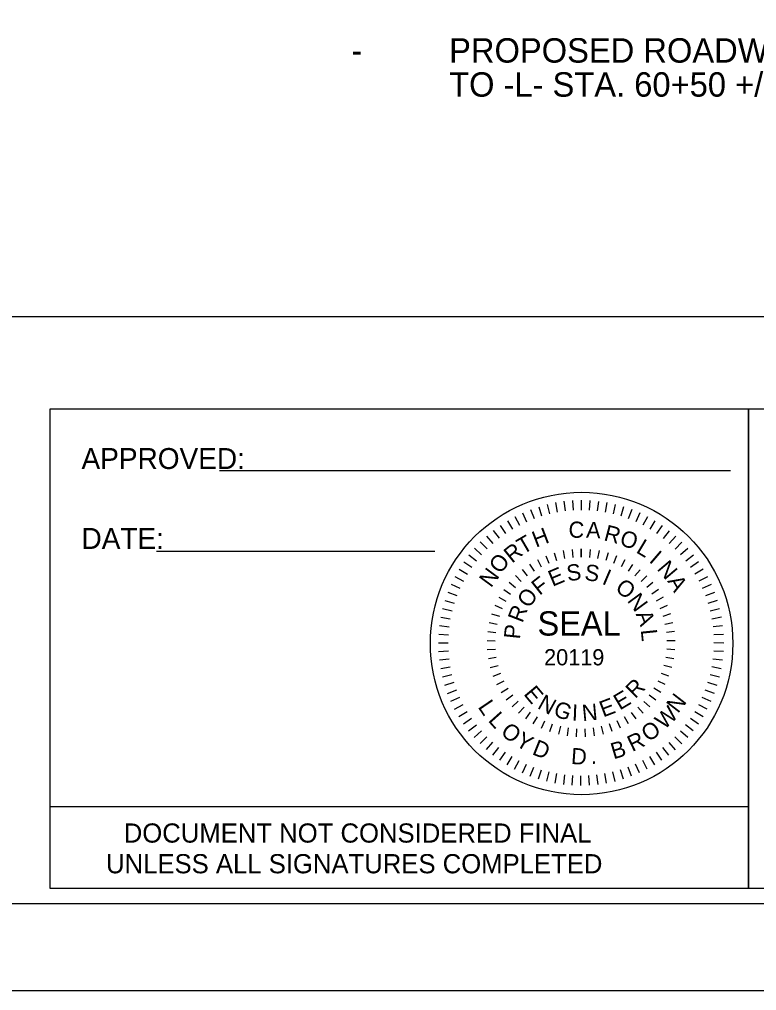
# Model space of a CAD drawing. Extents: x 764226 to 769781, y 650021 to 652521.
# Drawn here: x 767548.3 to 767759.5, y 651421.3 to 651699.7 of the extents above; entities that cross this region are included whole.
import ezdxf

# ---------------------------------------------------------------- set-up
doc = ezdxf.new("R2010")
doc.units = 0
for name, color, linetype in [('Default', 7, 'Continuous'), ('DEV BORDER CELL', 7, 'Continuous'), ('Scratch_Level_0', 7, 'Continuous'), ('Sheet Plot Border Outside CELL', 7, 'Continuous'), ('Sheet Sticker Exception Certification CELL', 7, 'Continuous')]:
    doc.layers.add(name, color=color, linetype=linetype)

msp = doc.modelspace()

# ---------------------------------------------------------------- linework, layer by layer
at = {"layer": 'Default'}
for p, q in [((767697.13, 651559.99), (767697.95, 651557.33)), ((767699.51, 651560.65), (767700.17, 651557.94)), ((767701.92, 651561.17), (767702.42, 651558.43)), ((767704.36, 651561.53), (767704.7, 651558.77)), ((767706.82, 651561.75), (767706.99, 651558.97)), ((767709.29, 651561.83), (767709.29, 651559.04)), ((767711.76, 651561.75), (767711.59, 651558.97)), ((767714.22, 651561.52), (767713.88, 651558.76)), ((767716.66, 651561.15), (767716.16, 651558.41)), ((767719.07, 651560.63), (767718.41, 651557.93)), ((767721.45, 651559.97), (767720.62, 651557.3)), ((767690.29, 651557.17), (767691.58, 651554.69)), ((767692.51, 651558.24), (767693.65, 651555.7)), ((767694.8, 651559.19), (767695.78, 651556.58)), ((767723.78, 651559.16), (767722.79, 651556.55)), ((767726.06, 651558.21), (767724.92, 651555.67)), ((767728.28, 651557.13), (767726.99, 651554.66)), ((767686.06, 651554.61), (767687.65, 651552.32)), ((767688.14, 651555.95), (767689.58, 651553.57)), ((767730.44, 651555.91), (767728.99, 651553.53)), ((767732.51, 651554.57), (767730.92, 651552.28)), ((767682.18, 651551.57), (767684.02, 651549.49)), ((767684.08, 651553.15), (767685.79, 651550.96)), ((767734.49, 651553.11), (767732.77, 651550.91)), ((767736.39, 651551.52), (767734.54, 651549.44)), ((767680.38, 651549.88), (767682.35, 651547.91)), ((767738.18, 651549.83), (767736.21, 651547.86)), ((767677.1, 651546.19), (767679.29, 651544.47)), ((767678.68, 651548.09), (767680.77, 651546.24)), ((767699.12, 651545.92), (767699.99, 651543.76)), ((767701.58, 651546.78), (767702.24, 651544.55)), ((767704.1, 651547.4), (767704.55, 651545.12)), ((767706.68, 651547.77), (767706.9, 651545.46)), ((767709.28, 651547.89), (767709.28, 651545.57)), ((767709.28, 651545.57), (767709.28, 651547.89)), ((767711.88, 651547.76), (767711.65, 651545.45)), ((767714.45, 651547.39), (767714.01, 651545.11)), ((767716.98, 651546.76), (767716.32, 651544.54)), ((767719.44, 651545.9), (767718.56, 651543.74)), ((767739.87, 651548.03), (767737.79, 651546.18)), ((767741.46, 651546.13), (767739.26, 651544.42)), ((767675.64, 651544.2), (767677.93, 651542.62)), ((767694.51, 651543.5), (767695.78, 651541.55)), ((767696.76, 651544.82), (767697.83, 651542.76)), ((767721.8, 651544.79), (767720.72, 651542.74)), ((767724.04, 651543.47), (767722.77, 651541.53)), ((767742.92, 651544.14), (767740.62, 651542.56)), ((767674.29, 651542.13), (767676.68, 651540.69)), ((767690.46, 651540.25), (767692.08, 651538.58)), ((767692.4, 651541.97), (767693.86, 651540.16)), ((767726.15, 651541.94), (767724.69, 651540.13)), ((767728.09, 651540.21), (767726.46, 651538.55)), ((767744.25, 651542.07), (767741.87, 651540.63)), ((767672, 651537.76), (767674.54, 651536.62)), ((767673.08, 651539.98), (767675.55, 651538.68)), ((767688.68, 651538.34), (767690.45, 651536.85)), ((767729.86, 651538.31), (767728.09, 651536.81)), ((767745.47, 651539.91), (767743, 651538.62)), ((767746.54, 651537.69), (767744, 651536.55)), ((767671.05, 651535.48), (767673.65, 651534.49)), ((767687.1, 651536.28), (767689.01, 651534.95)), ((767731.44, 651536.24), (767729.53, 651534.92)), ((767747.49, 651535.41), (767744.88, 651534.42)), ((767670.24, 651533.15), (767672.9, 651532.32)), ((767684.56, 651531.73), (767686.69, 651530.81)), ((767685.72, 651534.07), (767687.75, 651532.93)), ((767732.81, 651534.03), (767730.78, 651532.89)), ((767733.96, 651531.69), (767731.83, 651530.76)), ((767748.29, 651533.08), (767745.63, 651532.25)), ((767669.57, 651530.77), (767672.28, 651530.1)), ((767683.64, 651529.3), (767685.85, 651528.58)), ((767734.88, 651529.25), (767732.67, 651528.54)), ((767748.95, 651530.7), (767746.25, 651530.04)), ((767669.05, 651528.36), (767671.79, 651527.85)), ((767682.95, 651526.79), (767685.22, 651526.29)), ((767735.57, 651526.74), (767733.3, 651526.24)), ((767749.47, 651528.28), (767746.73, 651527.79)), ((767668.46, 651523.46), (767671.24, 651523.29)), ((767668.68, 651525.92), (767671.45, 651525.58)), ((767682.51, 651524.22), (767684.82, 651523.95)), ((767736, 651524.17), (767733.7, 651523.9)), ((767749.83, 651525.84), (767747.07, 651525.51)), ((767750.06, 651523.38), (767747.28, 651523.22)), ((767668.38, 651520.99), (767671.17, 651520.99)), ((767682.32, 651521.63), (767684.64, 651521.57)), ((767736.19, 651521.58), (767733.87, 651521.52)), ((767750.13, 651520.91), (767747.34, 651520.92)), ((767668.45, 651518.52), (767671.23, 651518.69)), ((767682.38, 651519.03), (767684.7, 651519.19)), ((767736.12, 651518.98), (767733.81, 651519.15)), ((767750.05, 651518.45), (767747.27, 651518.61)), ((767668.67, 651516.06), (767671.44, 651516.39)), ((767682.7, 651516.44), (767684.98, 651516.83)), ((767733.53, 651516.87), (767735.82, 651516.48)), ((767749.83, 651515.99), (767747.06, 651516.32)), ((767669.04, 651513.62), (767671.78, 651514.12)), ((767683.25, 651513.9), (767685.49, 651514.5)), ((767684.06, 651511.42), (767686.23, 651512.24)), ((767734.43, 651511.37), (767732.27, 651512.2)), ((767735.24, 651513.85), (767733, 651514.46)), ((767749.45, 651513.55), (767746.72, 651514.05)), ((767669.56, 651511.21), (767672.26, 651511.87)), ((767670.22, 651508.83), (767672.88, 651509.65)), ((767685.1, 651509.04), (767687.18, 651510.06)), ((767733.39, 651508.99), (767731.31, 651510.02)), ((767748.27, 651508.75), (767745.61, 651509.58)), ((767748.93, 651511.14), (767746.23, 651511.8)), ((767671.02, 651506.49), (767673.63, 651507.48)), ((767686.35, 651506.76), (767688.33, 651507.98)), ((767732.13, 651506.72), (767730.15, 651507.94)), ((767747.46, 651506.42), (767744.86, 651507.42)), ((767671.97, 651504.21), (767674.51, 651505.35)), ((767687.83, 651504.61), (767689.68, 651506.02)), ((767689.51, 651502.63), (767691.21, 651504.2)), ((767728.96, 651502.59), (767727.27, 651504.17)), ((767730.65, 651504.57), (767728.8, 651505.99)), ((767746.51, 651504.14), (767743.97, 651505.29)), ((767673.04, 651501.99), (767675.51, 651503.28)), ((767674.25, 651499.84), (767676.64, 651501.28)), ((767691.37, 651500.8), (767692.91, 651502.54)), ((767693.4, 651499.17), (767694.76, 651501.05)), ((767727.1, 651500.77), (767725.56, 651502.51)), ((767744.22, 651499.77), (767741.83, 651501.22)), ((767745.43, 651501.92), (767742.96, 651503.22)), ((767675.59, 651497.76), (767677.89, 651499.34)), ((767695.57, 651497.74), (767696.76, 651499.75)), ((767697.88, 651496.53), (767698.86, 651498.64)), ((767720.58, 651496.51), (767719.61, 651498.62)), ((767722.89, 651497.72), (767721.71, 651499.72)), ((767725.07, 651499.14), (767723.71, 651501.02)), ((767742.87, 651497.7), (767740.58, 651499.29)), ((767677.05, 651495.78), (767679.25, 651497.49)), ((767678.64, 651493.87), (767680.72, 651495.72)), ((767700.29, 651495.55), (767701.06, 651497.74)), ((767703.33, 651497.06), (767702.77, 651494.8)), ((767705.34, 651494.3), (767705.67, 651496.6)), ((767707.93, 651494.04), (767708.04, 651496.36)), ((767710.53, 651494.04), (767710.42, 651496.36)), ((767713.12, 651494.29), (767712.79, 651496.59)), ((767715.68, 651494.79), (767715.12, 651497.05)), ((767718.17, 651495.53), (767717.4, 651497.72)), ((767739.82, 651493.82), (767737.74, 651495.67)), ((767741.41, 651495.72), (767739.22, 651497.43)), ((767680.33, 651492.08), (767682.3, 651494.04)), ((767738.13, 651492.02), (767736.16, 651493.99)), ((767682.12, 651490.38), (767683.97, 651492.46)), ((767684.02, 651488.8), (767685.74, 651490.99)), ((767734.43, 651488.75), (767732.72, 651490.95)), ((767736.33, 651490.33), (767734.49, 651492.42)), ((767686, 651487.33), (767687.59, 651489.62)), ((767688.07, 651485.99), (767689.52, 651488.37)), ((767690.23, 651484.78), (767691.52, 651487.24)), ((767728.22, 651484.74), (767726.92, 651487.21)), ((767730.37, 651485.95), (767728.93, 651488.34)), ((767732.44, 651487.29), (767730.86, 651489.58)), ((767692.45, 651483.7), (767693.59, 651486.23)), ((767694.72, 651482.74), (767695.72, 651485.35)), ((767697.06, 651481.94), (767697.89, 651484.6)), ((767721.38, 651481.91), (767720.55, 651484.58)), ((767723.71, 651482.72), (767722.73, 651485.33)), ((767725.99, 651483.67), (767724.86, 651486.21)), ((767699.44, 651481.27), (767700.1, 651483.98)), ((767701.85, 651480.75), (767702.35, 651483.49)), ((767704.29, 651480.38), (767704.63, 651483.14)), ((767706.75, 651480.15), (767706.92, 651482.93)), ((767709.22, 651480.08), (767709.22, 651482.86)), ((767711.69, 651480.15), (767711.52, 651482.93)), ((767714.14, 651480.37), (767713.81, 651483.14)), ((767716.58, 651480.74), (767716.09, 651483.48)), ((767719, 651481.25), (767718.34, 651483.96))]:
    msp.add_line(p, q, dxfattribs=at)
at = {"layer": 'DEV BORDER CELL'}
for p, q in [((767605.7, 651570.37), (767752.04, 651570.37)), ((767757.19, 651564.55), (767757.19, 651450.55)), ((767587.58, 651547.29), (767667.37, 651547.29))]:
    msp.add_line(p, q, dxfattribs=at)
for points in [[(768112.34, 652496.28), (766612.34, 652496.28), (766612.34, 651446.28), (768112.34, 651446.28)], [(767557.15, 651588.05), (767757.19, 651588.05), (767757.19, 651450.55), (767557.15, 651450.55)], [(767757.19, 651588.05), (767871.19, 651588.05), (767871.19, 651450.55), (767757.19, 651450.55)]]:
    msp.add_lwpolyline(points, close=True, dxfattribs=at)
msp.add_circle((767709.41, 651520.78), 43.34, dxfattribs=at)
at = {"layer": 'Scratch_Level_0'}
msp.add_lwpolyline([(768062.34, 652446.28), (766662.34, 652446.28), (766662.34, 651496.28), (767541.19, 651496.28), (767541.19, 651614.55), (768062.34, 651614.55)], close=True, dxfattribs=at)
at = {"layer": 'Sheet Plot Border Outside CELL'}
msp.add_lwpolyline([(766449.34, 651421.28), (768137.34, 651421.28), (768137.34, 652521.28), (766449.34, 652521.28)], close=True, dxfattribs=at)
at = {"layer": 'Sheet Sticker Exception Certification CELL'}
for p, q in [((767557.15, 651450.55), (767557.15, 651474.05)), ((767557.15, 651474.05), (767757.19, 651474.05)), ((767757.19, 651474.04), (767757.19, 651450.54)), ((767757.19, 651450.55), (767557.15, 651450.55))]:
    msp.add_line(p, q, dxfattribs=at)

# ---------------------------------------------------------------- texts
at = {"layer": 'Default'}
for s, height, rotation, p in [('PROPOSED ROADWAY, AND SIDEWALKS, FROM -L- STA. 50+98 +/- ', 7, 359.9999, (767671.45, 651687.29)), ('-', 7, 359.9999, (767643.45, 651687.29)), ('TO -L- STA. 60+50 +/- (RT) (SEE SHEET TMP-16).', 7, 359.9999, (767671.45, 651677.53)), ('H', 4.64, 21.0146, (767696.33, 651548.22)), ('C', 4.64, 357.3039, (767705.57, 651551.19)), ('A', 4.64, 357.3039, (767710.64, 651551.1)), ('R', 4.64, 345.2946, (767715.56, 651550.41)), ('T', 4.64, 30.4466, (767692.6, 651546.2)), ('O', 4.64, 342.2378, (767720.05, 651549.07)), ('R', 4.64, 38.6075, (767689.47, 651543.61)), ('L', 4.64, 329.1015, (767724.77, 651547)), ('O', 4.64, 51.6643, (767686.11, 651540.49)), ('I', 4.64, 319.5261, (767728.51, 651544.3)), ('S', 4.64, 7.5951, (767705.44, 651538.6)), ('S', 4.64, 352.2989, (767710.08, 651538.98)), ('N', 4.64, 310.2316, (767730.83, 651542.11)), ('N', 4.64, 53.6237, (767683.44, 651536.57)), ('F', 4.64, 38.1876, (767697.37, 651534.39)), ('E', 4.64, 22.8914, (767701.08, 651537.01)), ('I', 4.64, 337.0026, (767715.01, 651537.97)), ('O', 4.64, 321.7064, (767718.75, 651536.16)), ('A', 4.64, 300.4641, (767733.89, 651538.68)), ('O', 4.64, 53.4838, (767694.28, 651530.65)), ('N', 4.64, 306.4101, (767722.32, 651533.05)), ('R', 4.64, 68.7801, (767692.44, 651526.48)), ('SEAL', 6.965, 359.947, (767696.78, 651523.05)), ('A', 4.64, 291.1139, (767724.86, 651529.25)), ('P', 4.64, 84.0763, (767691.73, 651521.88)), ('L', 4.64, 275.8176, (767726.36, 651524.66)), ('20119', 4.64, 359.947, (767698.67, 651514.52)), ('R', 4.64, 44.5119, (767724.78, 651504.77)), ('E', 4.64, 310.0171, (767692.61, 651506.23)), ('E', 4.64, 30.7408, (767720.36, 651501.54)), ('L', 4.64, 303.882, (767679.56, 651502.6)), ('N', 4.64, 330.8721, (767696.5, 651502.36)), ('G', 4.64, 339.6384, (767701.04, 651500.18)), ('E', 4.64, 20.7549, (767715.6, 651499.56)), ('N', 4.64, 52.154, (767737, 651500.56)), ('L', 4.64, 311.9538, (767682.43, 651498.62)), ('I', 4.64, 357.7332, (767706.57, 651498.69)), ('N', 4.64, 5.3628, (767709.72, 651498.53)), ('W', 4.64, 43.2714, (767733.1, 651495.9)), ('O', 4.64, 320.5966, (767685.95, 651494.96)), ('Y', 4.64, 329.2691, (767690.17, 651491.72)), ('O', 4.64, 34.3888, (767728.53, 651492.42)), ('D', 4.64, 338.2416, (767695, 651489.09)), ('B', 4.64, 16.5636, (767718.56, 651487.55)), ('R', 4.64, 25.5662, (767723.92, 651489.65)), ('D', 4.64, 356.0369, (767706.28, 651486.26)), ('.', 4.64, 3.7793, (767712.13, 651486.22))]:
    msp.add_text(s, height=height, rotation=rotation, dxfattribs=at).set_placement(p)
at = {"layer": 'DEV BORDER CELL'}
for s, p in [('APPROVED:  ', (767566.12, 651570.8)), ('DATE:  ', (767566.12, 651547.89))]:
    msp.add_text(s, height=6, dxfattribs=at).set_placement(p)
at = {"layer": 'Sheet Sticker Exception Certification CELL'}
for s, p in [('DOCUMENT NOT CONSIDERED FINAL', (767578.22, 651463.7)), ('UNLESS ALL SIGNATURES COMPLETED', (767573.15, 651454.9))]:
    msp.add_text(s, height=5.5, dxfattribs=at).set_placement(p)

doc.saveas('drawing.dxf')
